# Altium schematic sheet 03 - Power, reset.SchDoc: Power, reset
size A3; PageSetup: Record=PageOptions¦CenterHorizontal=True¦CenterVertical=True¦PrintScale=0.70¦XCorrection=1.00¦YCorrection=1.00¦PrintKind=0¦BorderSize=5000000¦LeftOffset=0¦BottomOffset=0¦Orientation=2¦PaperLength=4200¦PaperWidth=2970¦Scale=100¦PaperSource=7¦PrintQuality=600¦MediaType=1¦DitherType=10¦PaperKind=A4¦PrintScaleMode=1; Author: Juan Anzola; SheetNumber: 3; SheetTotal: 21
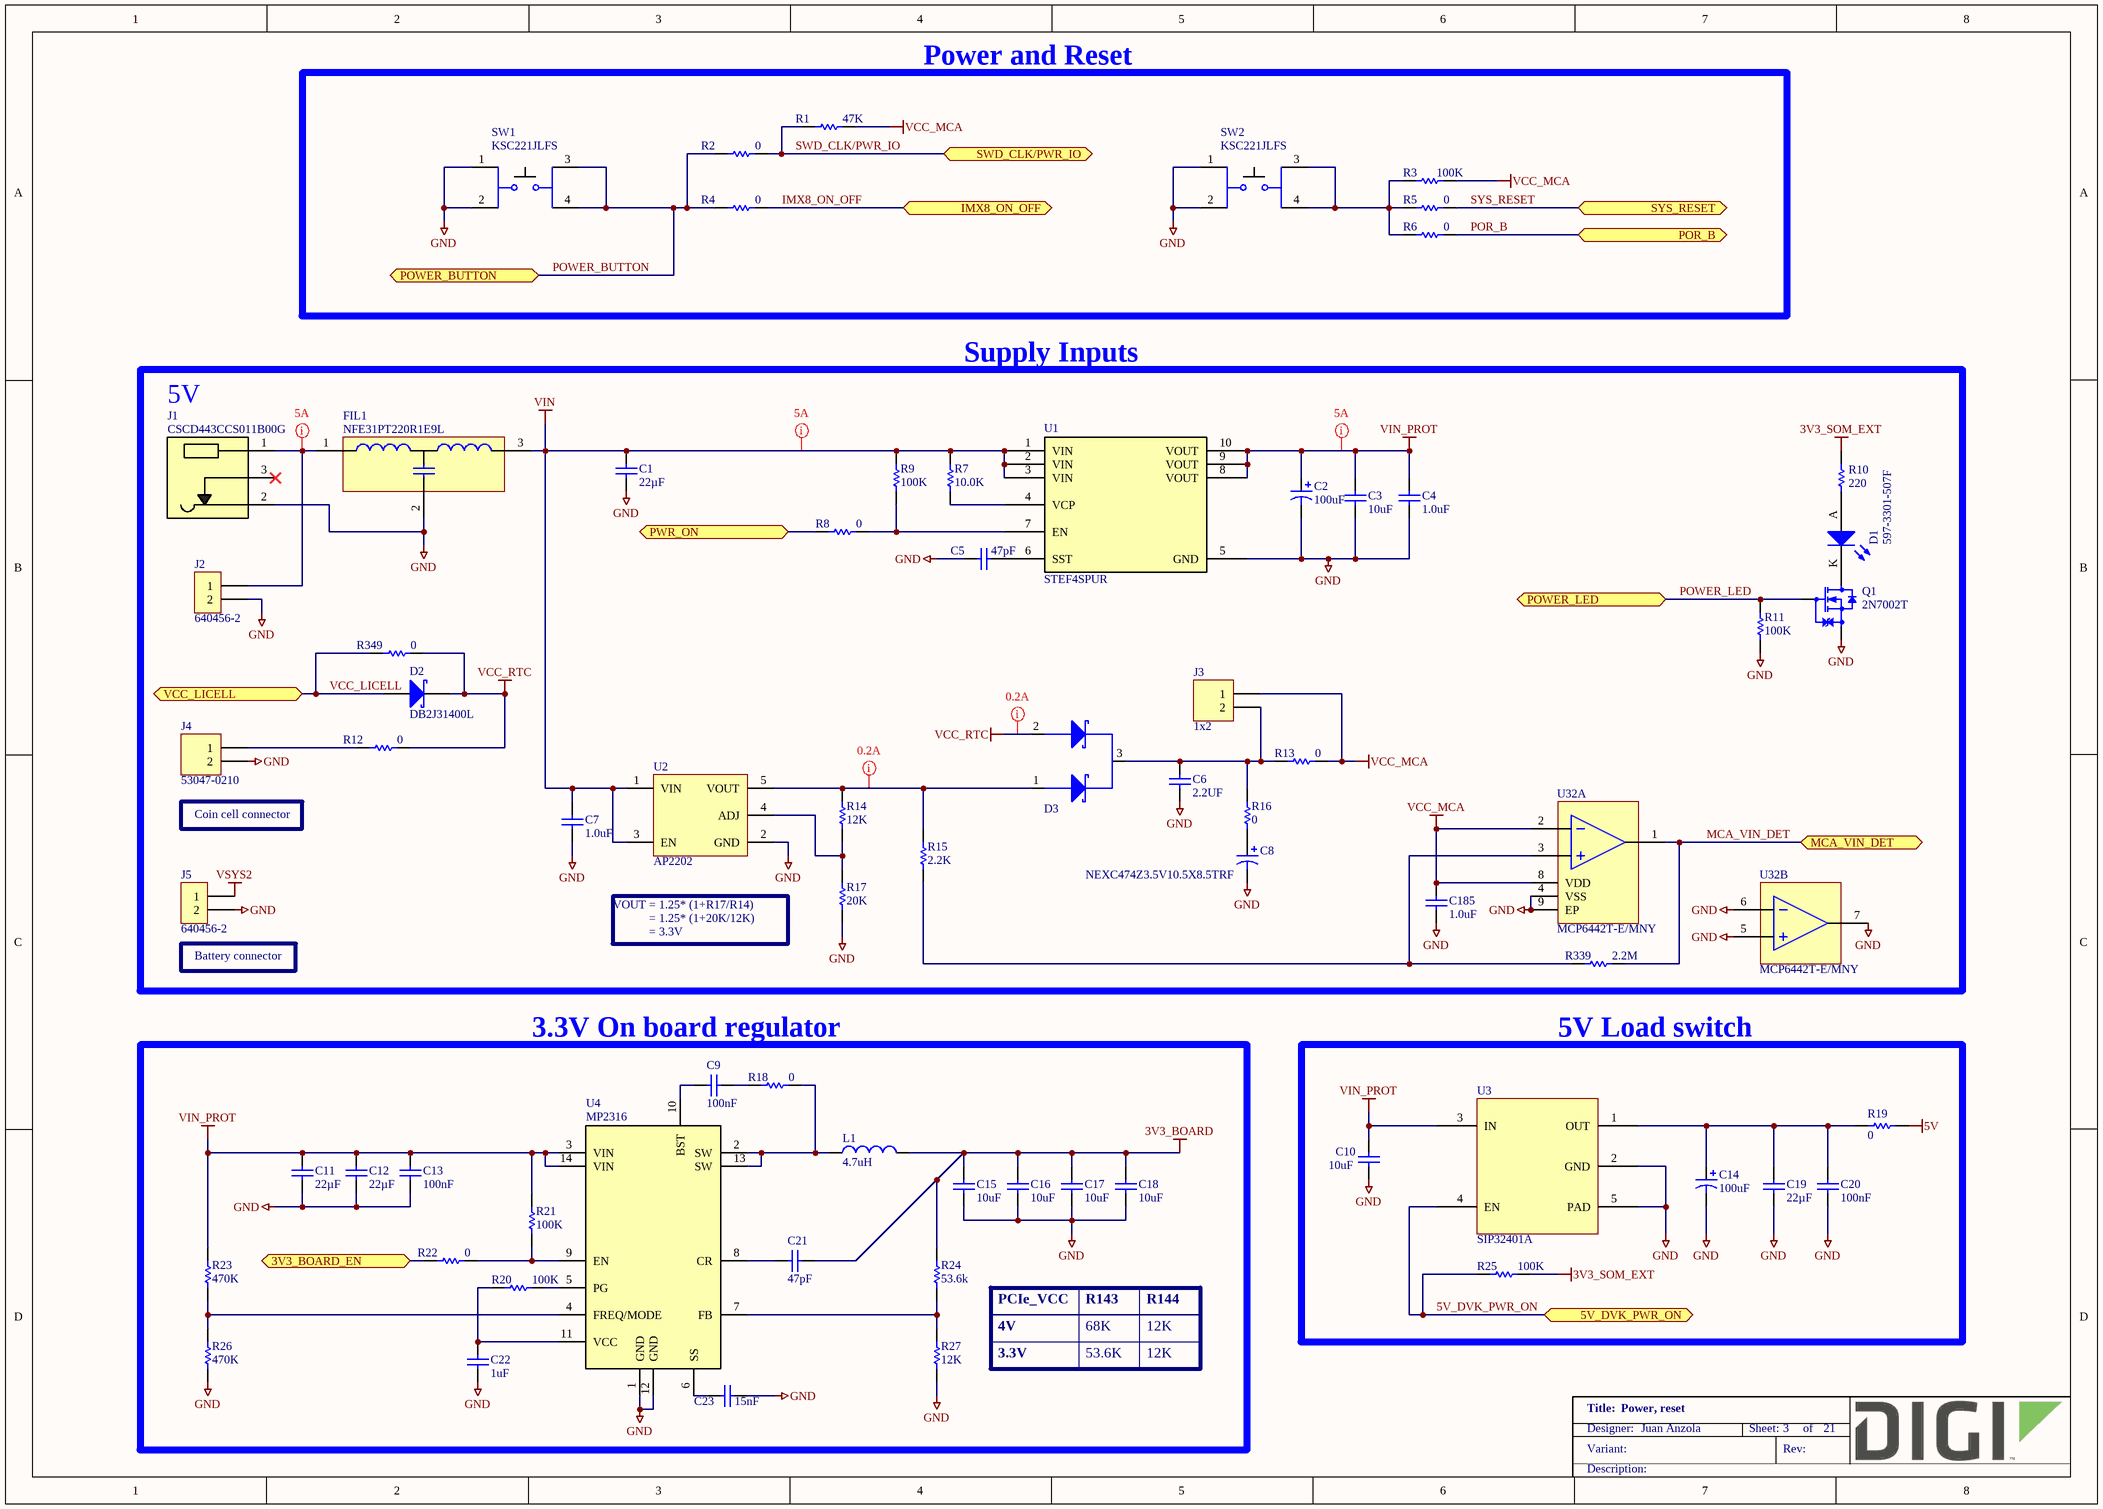
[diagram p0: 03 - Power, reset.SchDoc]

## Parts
C1  22µF  [CAPC1608X90N]
C2  100uF  [CAPMP3216X120N]
C3  10uF  [CAPC1005X55N]
C4  1.0uF  [CAPC1005X55N]
C5  47pF  [CAPC1005X55N]
C6  2.2UF  [CAPC1608X90N]
C7  1.0uF  [CAPC1005X55N]
C8  NEXC474Z3.5V10.5X8.5TRF  [NEXC474Z3.5V10.5X8.5TRF]
C9  100nF  [CAPC1005X55N]
C10  10uF  [CAPC1005X55N]
C11  22µF  [CAPC1608X90N]
C12  22µF  [CAPC1608X90N]
C13  100nF  [CAPC1005X55N]
C14  100uF  [CAPMP3216X120N]
C15  10uF  [CAPC2013X135N]
C16  10uF  [CAPC2013X135N]
C17  10uF  [CAPC2013X135N]
C18  10uF  [CAPC2013X135N]
C19  22µF  [CAPC1608X90N]
C20  100nF  [CAPC1005X55N]
C21  47pF  [CAPC1005X55N]
C22  1uF  [CAPC1608X90N]
C23  15nF  [CAPC1005X55N]
C185  1.0uF  [CAPC1005X55N]
D1  597-3301-507F  [LEDM3020X130N]
D2  DB2J31400L  [SODFL2513X80N]
D3  BAT54CWT1G  [SOT65P210X100-3AN]  (value not drawn)
FIL1  NFE31PT220R1E9L  [FIL_NFE31P]
J1  CSCD443CCS011B00G  [conn_CSCD443CCS011B00G]
J2  640456-2  [TE_640456-2]
J3  1x2  [FCI_68002-102HLF]
J4  Manufacturer_Part_Number: 53047-0210  [MOLEX_53047-0210_Flex]  (hidden comment: 1x2P)
J5  640456-2  [TE_640456-2]
L1  4.7uH  [IND_DG6045C]
Q1  2N7002T  [SOTFL50P160X80_GSD-3N]
R1  47K  [RESC1005X40N]
R2  0  [RESC1005X40N]
R3  100K  [RESC1005X40N]
R4  0  [RESC1005X40N]
R5  0  [RESC1005X40N]
R6  0  [RESC1005X40N]
R7  10.0K  [RESC1005X40N]
R8  0  [RESC1005X40N]
R9  100K  [RESC1005X40N]
R10  220  [RESC1005X40N]
R11  100K  [RESC1005X40N]
R12  0  [RESC1609X55N]
R13  0  [RESC1609X55N]
R14  12K  [RESC1609X55N]
R15  2.2K  [RESC1005X40N]
R16  0  [RESC1005X40N]
R17  20K  [RESC1609X55N]
R18  0  [RESC1609X55N]
R19  0  [RESC1609X55N]
R20  100K  [RESC1005X40N]
R21  100K  [RESC1005X40N]
R22  0  [RESC1005X40N]
R23  470K  [RESC1005X40N]
R24  53.6k  [RESC1609X55N]
R25  100K  [RESC1005X40N]
R26  470K  [RESC1005X40N]
R27  12K  [RESC1609X55N]
R339  2.2M  [RESC0603X28N]
R349  0  [RESC1609X55N]
SW1  KSC221JLFS  [SW_KSC221J]
SW2  KSC221JLFS  [SW_KSC221J]
U1  STEF4SPUR  [SON50P300X300X80-11T164X238N]
U2  AP2202  [SOT95P280X145-5N]
U3  SIP32401A  [SON50P120X160X60-5T55X91N]
U4  MP2316  [QFN_MPS_MP2316]
U32  MCP6442T-E/MNY  [SON50P300X200X80-9N]  (parts A,B of 2)

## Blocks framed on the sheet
Power and Reset: R1-R6 SW1 SW2
Supply Inputs: C1-C8 C185 D1-D3 FIL1 J1-J5 Q1 R7-R17 R339 R349 U1 U2 U32
3.3V On board regulator: C9 C11-C13 C15-C18 C21-C23 L1 R18 R20-R24 R26 R27 U4
5V Load switch: C10 C14 C19 C20 R19 R25 U3

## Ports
3V3_BOARD_EN (bidir), 5V_DVK_PWR_ON (bidir), IMX8_ON_OFF (bidir), MCA_VIN_DET (bidir), POR_B (bidir), POWER_BUTTON (bidir), POWER_LED (bidir), PWR_ON (bidir), SWD_CLK/PWR_IO (bidir), SYS_RESET (bidir), VCC_LICELL (bidir)

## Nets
3V3_BOARD: C15.2 C16.2 C17.2 C18.2 C21.2 L1.2 R24.2
3V3_SOM_EXT: R10.2 R25.2
5V: R19.2
GND: C1.1 C2.2 C3.1 C4.1 C5.1 C6.1 C7.1 C8.2 C10.1 C11.1 C12.1 C13.1 C14.2 C15.1 C16.1 C17.1 C18.1 C19.1 C20.1 C22.1 C23.1 C185.1 FIL1.2 J1.2 J2.2 J4.2 J5.2 Q1.S R11.2 R17.1 R26.1 R27.1 SW1.1 SW1.2 SW2.1 SW2.2 U1.5(GND) U2.2(GND) U3.2(GND) U3.5(PAD) U4.1(GND) U4.12(GND) U32.4(VSS) U32.5(VINB+) U32.6(VINB-) U32.7(VOUTB) U32.9(EP)
VCC_MCA: C185.2 J3.1 R1.2 R3.2 R13.2 U32.2(VIN-) U32.8(VDD)
VCC_RTC: D2.K D3.2 R12.2 R349.2
VIN: C1.2 C7.2 FIL1.3(GND) R7.2 R9.2 U1.1(VIN) U1.2(VIN) U1.3(VIN) U2.1(VIN) U2.3(EN)
VIN_PROT: C2.1 C3.2 C4.2 C10.2 C11.2 C12.2 C13.2 R21.2 R23.2 U1.8(VOUT) U1.9(VOUT) U1.10(VOUT) U3.3(IN) U4.3(VIN) U4.14(VIN)
VSYS2: J5.1
3V3_BOARD_EN: R22.1 ; port 3V3_BOARD_EN
5V_DVK_PWR_ON: R25.1 U3.4(EN) ; port 5V_DVK_PWR_ON
IMX8_ON_OFF: R4.2 ; port IMX8_ON_OFF
MCA_VIN_DET: R339.2 U32.1(VOUT) ; port MCA_VIN_DET
POR_B: R6.2 ; port POR_B
POWER_BUTTON: R2.1 R4.1 SW1.3 SW1.4 ; port POWER_BUTTON
POWER_LED: Q1.G R11.1 ; port POWER_LED
PWR_ON: R8.1 ; port PWR_ON
SWD_CLK/PWR_IO: R1.1 R2.2 ; port SWD_CLK/PWR_IO
SYS_RESET: R5.2 ; port SYS_RESET
VCC_LICELL: D2.A R349.1 ; port VCC_LICELL
NetC5_2: C5.2 U1.6(SST)
NetC6_2: C6.2 D3.3 J3.2 R13.1 R16.2
NetC8_1: C8.1 R16.1
NetC9_1: C9.1 U4.10(BST)
NetC9_2: C9.2 R18.1
NetC14_1: C14.1 C19.2 C20.2 R19.1 U3.1(OUT)
NetC21_1: C21.1 U4.8(CR)
NetC22_2: C22.2 R20.1 U4.11(VCC)
NetC23_2: C23.2 U4.6(SS)
NetD1_A: D1.A R10.1
NetD1_K: D1.K Q1.D
NetD3_1: D3.1 R14.2 R15.2 U2.5(VOUT)
NetFIL1_1: FIL1.1(GND) J1.1 J2.1
NetJ4_1: J4.1 R12.1
NetL1_1: L1.1 R18.2 U4.2(SW) U4.13(SW)
NetR3_1: R3.1 R5.1 R6.1 SW2.3 SW2.4
NetR7_1: R7.1 U1.4(VCP)
NetR8_2: R8.2 R9.1 U1.7(EN)
NetR14_1: R14.1 R17.2 U2.4(ADJ)
NetR15_1: R15.1 R339.1 U32.3(VIN+)
NetR20_2: R20.2 U4.5(PG)
NetR21_1: R21.1 R22.2 U4.9(EN)
NetR23_1: R23.1 R26.2 U4.4(FREQ/MODE)
NetR24_1: R24.1 R27.2 U4.7(FB)

Not connected (* = marked no-connect by the designer): J1 3*

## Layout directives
net class 0.2A: NetD3_1, VCC_RTC
net class 5A: NetFIL1_1, VIN, VIN_PROT

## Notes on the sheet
- 5V
- Coin cell connector
- (near J5) Battery connector
- VOUT = 1.25* (1+R17/R14)
  = 1.25* (1+20K/12K)
  = 3.3V
- PCIe_VCC
- R143
- R144
- 4V
- 3.3V
- 68K
- 53.6K
- 12K

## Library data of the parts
C1 = 1000998: CAP CER 22UF 10V 20% X5R 0603; Part_Type: Capacitor; Manufacturer: Samsung; Manufacturer_Part_Number: CL10A226MP8NUNE; Manufacturer_Alt_1: TDK Corporation; Manufacturer_Alt_1_Part_Number: C1608X5R1A226M080AC; Digi_PN: 14050684; Component_Life_Cycle_State: Reviewed; Area: 2,27; Tolerance: 20
C2 C14 = 1001196: CAP TANT 100UF 6.3V 20% 1206; Part_Type: Capacitor; Manufacturer: Rohm; Manufacturer_Part_Number: TCTAL0J107M8R; Digi_PN: 14050490; Component_Life_Cycle_State: Reviewed; Area: 8.01; Project: CCWMX6_SBC board
C3 C10 = 1001168: CAP CER 10UF 10V 20% X5R 0402; Part_Type: Capacitor; Manufacturer: Samsung; Manufacturer_Part_Number: CL05A106MP5NUNC; Digi_PN: 14050689; Component_Life_Cycle_State: Reviewed; Area: 0.95; Project: CCWMX6_SBC board
C4 = 1001167: CAP CER 1UF 10V 10% X5R 0402; Part_Type: Capacitor; Manufacturer: Murata; Manufacturer_Part_Number: GRM155R61A105KE15D; Digi_PN: 14050399; Component_Life_Cycle_State: Reviewed; Area: 0,95; Project: CCWMX6_SBC board
C5 = 1000007: CAP 47pF 50V 5% NP0 0402; Part_Type: Capacitor; Manufacturer: Murata; Manufacturer_Part_Number: GRM1555C1H470JA01D; Manufacturer_Alt_1: AVX Corporation; Manufacturer_Alt_1_Part_Number: 04025A470JAT2A; Note: 14050747 is Digi No. for GE WDNU; Digi_PN: 14050309; Component_Life_Cycle_State: CAD Reviewed; Area: 0,95; Temp_Coef: C0G, NP0
C6 = 1001303: CAP CER 2.2UF 16V 10% X5R 0603; Part_Type: Capacitor; Manufacturer: TDK Corporation; Manufacturer_Part_Number: C1608X5R1C225K080AB; Digi_PN: 14050730; Component_Life_Cycle_State: Reviewed; Area: 2,27; Project: Pinnacle
C7 = 1000073: CAP CER 1UF 6.3V 20% X5R 0402; Part_Type: Capacitor; Manufacturer: Murata; Manufacturer_Part_Number: GRM155R60J105ME19D; Digi_PN: 14050543; Component_Life_Cycle_State: Proven; Area: 0.95; Project: Adjustable Foundation
C8 = 1002775: SMCAP, 0.47F 3.5V SUPERCAP 8.5x10.5x10.8mm SMT; Part_Type: Capacitor; Manufacturer: NIC; Digi_PN: 14050629; Component_Life_Cycle_State: Pending
C9 C13 = 1000006: CAP 100nF 16V 10% X7R 0402; Part_Type: Capacitor; Manufacturer: Murata; Manufacturer_Part_Number: GRM155R71C104KA88D; Digi_PN: 14050552; Component_Life_Cycle_State: CAD Reviewed; Area: 0.95; Project: KITT; Tolerance: 10
C11 C12 C19 = 1000998: CAP CER 22UF 10V 20% X5R 0603; Part_Type: Capacitor; Manufacturer: Samsung; Manufacturer_Part_Number: CL10A226MP8NUNE; Manufacturer_Alt_1: TDK Corporation; Manufacturer_Alt_1_Part_Number: C1608X5R1A226M080AC; Digi_PN: 14050684; Component_Life_Cycle_State: Reviewed; Area: 2.27; Project: ConnectCore i.MX6 module; Tolerance: 20
C15-C18 = 1000111: CAP CER 10UF 16V 10% X5R 0805; Part_Type: Capacitor; Manufacturer: Murata; Manufacturer_Part_Number: GRM21BR61C106KE15L; Digi_PN: 14050701; Component_Life_Cycle_State: Proven; Area: 3.99; Project: Adjustable Foundation; Tolerance: 10
C20 = 1000006: CAP 100nF 16V 10% X7R 0402; Part_Type: Capacitor; Manufacturer: Murata; Manufacturer_Part_Number: GRM155R71C104KA88D; Component_Life_Cycle_State: CAD Reviewed; Area: 0.95; Project: KITT; Tolerance: 10; Digi_PN: 14050552
C21 = 1000007: CAP 47pF 50V 5% NP0 0402; Part_Type: Capacitor; Manufacturer: Murata; Manufacturer_Part_Number: GRM1555C1H470JA01D; Manufacturer_Alt_1: AVX Corporation; Manufacturer_Alt_1_Part_Number: 04025A470JAT2A; Note: 14050747 is Digi No. for GE WDNU; Digi_PN: 14050309; Component_Life_Cycle_State: CAD Reviewed; Area: 0.95; Project: KITT; Temp_Coef: C0G, NP0
C22 = 1000110: CAP CER 1UF 25V 10% X5R 0603; Part_Type: Capacitor; Manufacturer: Murata; Manufacturer_Part_Number: GRM188R61E105KA12D; Manufacturer_Alt_1: AVX Corporation; Manufacturer_Alt_1_Part_Number: TMK107BJ105KA-T; Note: 14050758  = Digi No. for GE WDNU; Digi_PN: 14050618; Component_Life_Cycle_State: Reviewed; Area: 2.27; Project: Adjustable Foundation
C23 = 1000512: CAP CER 0.015UF 16V 10% X7R 0402; Part_Type: Capacitor; Manufacturer: Murata; Manufacturer_Part_Number: GRM155R71C153KA01D; Digi_PN: 14050713; Component_Life_Cycle_State: CAD Reviewed; Area: 0.95; Project: Cellular Proof of Concept
C185 = 1000073: CAP CER 1UF 6.3V 20% X5R 0402; Part_Type: Capacitor; Manufacturer: Murata; Manufacturer_Part_Number: GRM155R60J105ME19D; Digi_PN: 14050543; Component_Life_Cycle_State: Proven; Area: 0,95
D1 = 1001189: LED GREEN 573NM 1208 SMD; Manufacturer: Dialight; Digi_PN: 17050183; Component_Life_Cycle_State: Reviewed; Area: 6; Project: CCWMX6_SBC board; Note: 17050846 = Digi PN for GE WDNU II
D2 = 1002592: DIODE SCHOTTKY 30V 30MA SMINI2; Part_Type: Diodes; Manufacturer: Panasonic - ECG; Digi_PN: 17000142; Component_Life_Cycle_State: Reviewed; Area: 6,06; Project: DIGI CC8X SOM
D3 = 1000794: DIODE SCHOTTKY 30V 200MA SOT323; Part Number: SDS1920004; Manufacturer: Fairchild Semiconductor; Manufacturer Alt 1: none; Manufacturer Part Num: 0082610201; Part_Type: Diodes; Digi_PN: 17050561; Component_Life_Cycle_State: CAD Reviewed; Area: 7,68; Project: SmartMeter2
FIL1 = 1002745: FILTER LC(T) 22PF SMD; Manufacturer: Murata; Digi_PN: 21000602; Component_Life_Cycle_State: Created; Area: 15
J1 = 1001105: DC Power Jack; Part_Type: Connector; Manufacturer: Bobbintron Electrical Corp; Digi_PN: 18000302; Component_Life_Cycle_State: Reviewed; Area: 137; Project: CCWMX6_SBC board
J2 J5 = 1002003: CONN HEADER VERT 2POS .100 TIN; Part_Type: Connector; Manufacturer: TE Connectivity; Digi_PN: 18050128; Component_Life_Cycle_State: Created; Area: 29,05; Project: iMX6UL+PMIC
J3 = 1001128: CONN HEADER 2POS .100" SGL GOLD; Part_Type: Connector; Manufacturer: Samtec; Manufacturer_Part_Number: TSW-102-07-G-S; Digi_PN: 00120002; Component_Life_Cycle_State: Reviewed; Area: 12,9032
J4 = 1001136: CONN HEADER 2POS 1.25MM VERT TIN; Part_Type: Connector; Manufacturer: Molex; Component_Life_Cycle_State: Reviewed; Area: 13.6; Project: CCWMX6_SBC board; Digi_PN: 18050343
L1 = 1002747: FIXED IND 4.7UH 4.5A 27.6 MOHM; Manufacturer: Murata; Manufacturer_Part_Number: 1255AY-4R7M=P3; Digi_PN: 21000603; Component_Life_Cycle_State: Reviewed; Area: 49
Q1 = 1000715: MOSFET N-CH 60V 115MA SOT-523F; Part_Type: Transistor; Manufacturer: Fairchild Semiconductor; Digi_PN: 17050797; Component_Life_Cycle_State: CAD Reviewed; Area: 3.06; Project: SmartMeter2; Note: 17050841 = Digi No. for GE WDNU
R1 = 1001155: RES 47.0K OHM 1/16W 1% 0402 SMD; Part_Type: Resistor; Manufacturer: Vishay Dale; Manufacturer_Part_Number: CRCW040247K0FKED; Digi_PN: 13050646; Component_Life_Cycle_State: Reviewed; Area: 0.95; Project: CCWMX6_SBC board
R2 R4-R6 R8 R22 = 1000076: RES 0.0 OHM 1/10W 0402 SMD; Part_Type: Resistor; Manufacturer: Panasonic - ECG; Manufacturer_Part_Number: ERJ-2GE0R00X; Component_Life_Cycle_State: Proven; Area: 0.95; Project: Adjustable Foundation; Power_WV_SRF: 10; Digi_PN: 13050387
R3 = 1000480: RES 100K OHM 1/10W 1% 0402 SMD; Part_Type: Resistor; Manufacturer: Panasonic - ECG; Manufacturer_Part_Number: ERJ-2RKF1003X; Digi_PN: 13051063; Component_Life_Cycle_State: CAD Reviewed; Area: 0,95; Project: KITT; Power_WV_SRF: 100
R7 = 1000537: RES 10.0K OHM 1/10W 1% 0402 SMD; Part_Type: Resistor; Manufacturer: Panasonic - ECG; Manufacturer_Part_Number: ERJ-2RKF1002X; Component_Life_Cycle_State: CAD Reviewed; Area: 0.95; Project: KITT; Power_WV_SRF: 100; Digi_PN: 13051084
R9 = 1000480: RES 100K OHM 1/10W 1% 0402 SMD; Part_Type: Resistor; Manufacturer: Panasonic - ECG; Manufacturer_Part_Number: ERJ-2RKF1003X; Digi_PN: 13051063; Component_Life_Cycle_State: CAD Reviewed; Area: 0,95; Power_WV_SRF: 100
R10 = 1001154: RES 220 OHM 1/16W 1% 0402 SMD; Part_Type: Resistor; Manufacturer: Yageo; Manufacturer_Part_Number: RC0402FR-07220RL; Digi_PN: 13050623; Component_Life_Cycle_State: Reviewed; Area: 0.95; Project: CCWMX6_SBC board
R11 R20 R21 R25 = 1000480: RES 100K OHM 1/10W 1% 0402 SMD; Part_Type: Resistor; Manufacturer: Panasonic - ECG; Manufacturer_Part_Number: ERJ-2RKF1003X; Digi_PN: 13051063; Component_Life_Cycle_State: CAD Reviewed; Area: 0.95; Project: KITT; Power_WV_SRF: 100
R12 R13 R18 R349 = 1000208: RES 0.0 OHM 1/10W 0603; Part_Type: Resistor; Manufacturer: Panasonic - ECG; Manufacturer_Part_Number: ERJ-3GEY0R00V; Note: 13051103 = Digi No. for GE WDNU; Digi_PN: 13050568; Component_Life_Cycle_State: Reviewed; Area: 2,5; Voltage: 75V
R14 = 1001200: RES 12.0K OHM 1/10W 1% 0603 SMD; Part_Type: Resistor; Manufacturer: Yageo; Manufacturer_Part_Number: RC0603FR-0712KL; Digi_PN: 13050531; Component_Life_Cycle_State: Reviewed; Area: 2,5; Project: LuCoV2; Power_WV_SRF: 100; Tolerance: 1
R15 = 1001156: RES 2.20K OHM 1/16W 1% 0402 SMD; Part_Type: Resistor; Manufacturer: Yageo; Manufacturer_Part_Number: RC0402FR-072K2L; Note: 13051099 = Digi No. for GE WDNU; Digi_PN: 13050699; Component_Life_Cycle_State: Reviewed; Area: 0,95
R16 = 1000076: RES 0.0 OHM 1/10W 0402 SMD; Part_Type: Resistor; Manufacturer: Panasonic - ECG; Manufacturer_Part_Number: ERJ-2GE0R00X; Digi_PN: 13050387; Component_Life_Cycle_State: Proven; Area: 0,95; Power_WV_SRF: 10
R17 = 1000142: RES 20K OHM 1/10W 5% 0603 SMD; Part_Type: Resistor; Manufacturer: Panasonic - ECG; Manufacturer_Part_Number: ERJ-3GEYJ203V; Digi_PN: 13050013; Component_Life_Cycle_State: Reviewed; Area: 2,5; Project: Adjustable Foundation; Power_WV_SRF: 100; Tolerance: 5
R19 = 1000208: RES 0.0 OHM 1/10W 0603; Part_Type: Resistor; Manufacturer: Panasonic - ECG; Manufacturer_Part_Number: ERJ-3GEY0R00V; Note: 13051103 = Digi No. for GE WDNU; Digi_PN: 13050568; Component_Life_Cycle_State: Reviewed; Area: 2.5; Project: Adjustable Foundation; Voltage: 75V
R23 R26 = 1000701: RES 470K OHM 1/10W 1% 0402 SMD; Part_Type: Resistor; Manufacturer: Panasonic - ECG; Manufacturer_Part_Number: ERJ-2RKF4703X; Digi_PN: 13051092; Component_Life_Cycle_State: CAD Reviewed; Area: 0.95; Project: KITT; Power_WV_SRF: 100
R24 = 1001518: RES 53.6K OHM 1/10W 1% 0603 SMD; Part_Type: Resistor; Manufacturer: Panasonic - ECG; Manufacturer_Part_Number: ERJ-3EKF5362V; Digi_PN: 13051064; Component_Life_Cycle_State: Reviewed; Area: 2.5; Project: WDNU-II
R27 = 1001200: RES 12.0K OHM 1/10W 1% 0603 SMD; Part_Type: Resistor; Manufacturer: Yageo; Manufacturer_Part_Number: RC0603FR-0712KL; Digi_PN: 13050531; Component_Life_Cycle_State: Reviewed; Area: 2.5; Project: LuCoV2; Power_WV_SRF: 100; Tolerance: 1
R339 = 1000980: RES 2.2M OHM 1/20W 5% 0201 SMD; Part_Type: Resistor; Manufacturer: Rohm; Manufacturer_Part_Number: MCR006YZPJ225; Manufacturer_Alt_1: Panasonic - ECG; Manufacturer_Alt_1_Part_Number: ERJ-1GEJ225C; Digi_PN: 13050884; Component_Life_Cycle_State: Reviewed; Area: 1,73; Power_WV_SRF: 50; Tolerance: 5
SW1 SW2 = 1001124: SWITCH TACTILE SPST-NO 0.05A 32V; Manufacturer: ITT; Digi_PN: 22000059; Component_Life_Cycle_State: Reviewed; Area: 37; Project: CCWMX6_SBC board; Note: 22000295 = Digi No. for GE WDNU
U1 = 1002744: IC ELECTRONIC FUSE 10VFDFPN; Manufacturer: STMicroelectronics; Digi_PN: 16000208; Component_Life_Cycle_State: Created; Area: 14,77
U2 = 1001979: IC REG LDO ADJ 0.15A SOT25; Part_Type: Regulator; Manufacturer: Diodes, Inc.; Manufacturer_Part_Number: AP2202K-ADJTRG1; Digi_PN: 17050874; Component_Life_Cycle_State: Created; Area: 8,9; Project: iMX6UL+PMIC
U3 = 1001857: IC SW W/CTRL SLEW RATE 4TDFN; Manufacturer: Vishay Siliconix; Manufacturer_Part_Number: SIP32401ADNP-T1GE4; Component_Life_Cycle_State: Reviewed; Area: 4.93; Project: CCWMX6_SBC board; Digi_PN: 16052004
U4 = 1001907: IC REG BUCK ADJ 3A SYNC; Manufacturer: Linear Technology; Manufacturer_Part_Number: MP2316GD; Digi_PN: 17050862; Component_Life_Cycle_State: Reviewed; Area: 9.375; Project: CCWMX6_SBC board
U32 = 1000217: IC OPAMP DUAL 1.6V 9KHZ 8TDFN; Manufacturer: Microchip; Digi_PN: 16000212; Component_Life_Cycle_State: Reviewed; Area: 7,4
